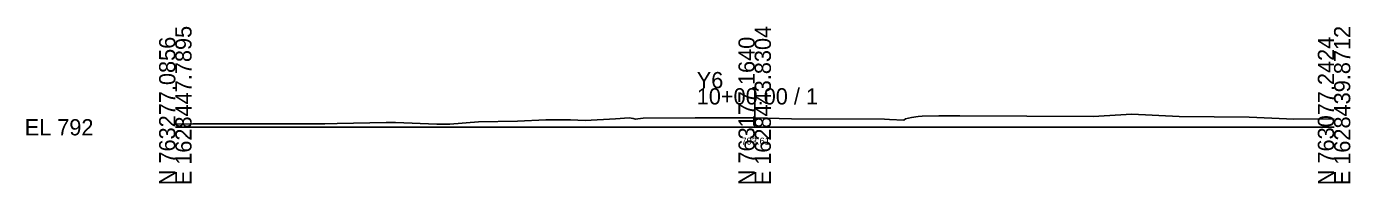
# Model space of a CAD drawing. Extents: x -26 to 203, y -10 to 6017.
# Drawn here: x -25.7 to 202.8, y -9.7 to 17.4 of the extents above; entities that cross this region are included whole.
import ezdxf

# ---------------------------------------------------------------- set-up
doc = ezdxf.new("R2010")
doc.units = 0
for name, color, linetype in [('Default', 7, 'Continuous'), ('Exist Cross Section Cell', 7, 'Continuous'), ('Exist XS Center Line Elevation Label', 7, 'Continuous'), ('Exist XS Ground Line', 7, 'Continuous')]:
    doc.layers.add(name, color=color, linetype=linetype)

msp = doc.modelspace()

# ---------------------------------------------------------------- linework, layer by layer
at = {"layer": 'Exist Cross Section Cell'}
for p, q in [((100, 0), (100, 6.73)), ((0, 0), (100, 0)), ((100, 0), (200, 0))]:
    msp.add_line(p, q, dxfattribs=at)
at = {"layer": 'Exist XS Ground Line'}
msp.add_lwpolyline([(0, 0.51), (3.03, 0.57), (3.48, 0.57), (6.63, 0.58), (8.46, 0.59), (18.2, 0.6), (19.46, 0.59), (25.82, 0.62), (27.96, 0.67), (36.4, 0.84), (37.98, 0.84), (45.16, 0.54), (47.4, 0.55), (52.3, 0.91), (59.06, 1.05), (63.94, 1.27), (68.2, 1.3), (70.76, 1.15), (76, 1.46), (78.34, 1.64), (79.04, 1.53), (79.42, 1.39), (79.81, 1.43), (80.73, 1.56), (89.74, 1.63), (99.11, 1.63), (100, 1.61), (106.36, 1.47), (122.38, 1.37), (123.24, 1.32), (125.73, 1.24), (126, 1.47), (126.54, 1.55), (127.09, 1.68), (128.23, 1.83), (128.89, 1.9), (131.78, 1.97), (135.41, 1.98), (146.97, 1.91), (158.43, 1.87), (165.11, 2.24), (173.25, 1.84), (185.36, 1.77), (189.28, 1.59), (193.03, 1.38), (200, 1.48)], dxfattribs=at)

# ---------------------------------------------------------------- texts
at = {"layer": 'Default'}
msp.add_text('-', height=0.0001, dxfattribs=at).set_placement((0, 0))
at = {"layer": 'Exist Cross Section Cell'}
for s, p in [('E 1628447.7895', (2.8, -10)), ('E 1628443.8304', (102.8, -10)), ('E 1628439.8712', (202.8, -10)), ('N 763277.0856', (0, -10)), ('N 763177.1640', (100, -10)), ('N 763077.2424', (200, -10))]:
    msp.add_text(s, height=2.8, rotation=90, dxfattribs=at).set_placement(p)
for s, p in [('Y6', (90, 6.73)), ('10+00.00 / 1', (90, 3.93)), ('EL 792', (-26, -1.4))]:
    msp.add_text(s, height=2.8, dxfattribs=at).set_placement(p)
at = {"layer": 'Exist XS Center Line Elevation Label'}
msp.add_text('793.61', height=1.2, dxfattribs=at).set_placement((97.71, -2.99))

doc.saveas('drawing.dxf')
